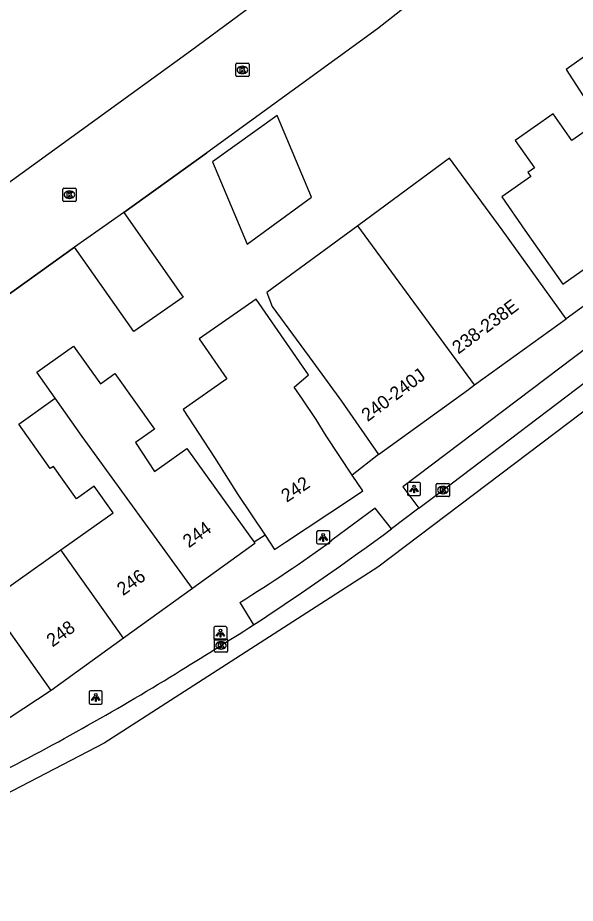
# Model space of a CAD drawing. Extents: x 159265 to 160143, y 383413 to 384319.
# Drawn here: x 159435.2 to 159477.4, y 383435.6 to 383502.5 of the extents above; entities that cross this region are included whole.
import ezdxf

# ---------------------------------------------------------------- set-up
doc = ezdxf.new("R2010")
doc.units = 0
for name, color, linetype in [('IMGEO_Kolk', 7, 'Continuous'), ('IMGEO_Lichtpunt', 7, 'Continuous'), ('IMGEO_Muur', 7, 'Continuous'), ('IMGEO_Pand', 7, 'Continuous'), ('IMGEO_Pand_nummerreeks', 7, 'Continuous'), ('IMGEO_Rijbaan_lokaal_gesloten', 7, 'Continuous'), ('IMGEO_Rijbaan_lokaal_open', 7, 'Continuous'), ('IMGEO_Rijbaan_regionaal_open', 7, 'Continuous'), ('IMGEO_Voetpad_open', 7, 'Continuous')]:
    doc.layers.add(name, color=color, linetype=linetype)

msp = doc.modelspace()

# ---------------------------------------------------------------- linework, layer by layer
at = {"layer": 'IMGEO_Kolk'}
for p, q in [((159451.715, 383498.137), (159451.715, 383498.989)), ((159451.79, 383499.063), (159452.642, 383499.063)), ((159452.716, 383498.989), (159452.716, 383498.137)), ((159452.226, 383498.283), (159452.201, 383498.283)), ((159452.203, 383498.843), (159452.228, 383498.843)), ((159452.642, 383498.063), (159451.79, 383498.063)), ((159438.627, 383488.701), (159438.627, 383489.553)), ((159438.702, 383489.627), (159439.554, 383489.627)), ((159439.628, 383489.553), (159439.628, 383488.701)), ((159439.138, 383488.847), (159439.113, 383488.847)), ((159439.115, 383489.407), (159439.14, 383489.407)), ((159439.554, 383488.627), (159438.702, 383488.627)), ((159466.884, 383466.372), (159466.884, 383467.224)), ((159466.959, 383467.298), (159467.811, 383467.298)), ((159467.372, 383467.078), (159467.397, 383467.078)), ((159467.885, 383467.224), (159467.885, 383466.372)), ((159467.811, 383466.298), (159466.959, 383466.298)), ((159467.395, 383466.518), (159467.37, 383466.518)), ((159450.097, 383454.623), (159450.097, 383455.475)), ((159450.172, 383455.549), (159451.024, 383455.549)), ((159451.098, 383455.475), (159451.098, 383454.623)), ((159450.608, 383454.769), (159450.583, 383454.769)), ((159450.585, 383455.329), (159450.61, 383455.329)), ((159451.024, 383454.549), (159450.172, 383454.549))]:
    msp.add_line(p, q, dxfattribs=at)
for points in [[(159451.715, 383498.137), (159451.715, 383498.989)], [(159451.79, 383499.063), (159452.642, 383499.063)], [(159452.716, 383498.989), (159452.716, 383498.137)], [(159452.036, 383498.763), (159452.159, 383498.763), (159452.159, 383498.612), (159452.289, 383498.763), (159452.453, 383498.763), (159452.307, 383498.612), (159452.46, 383498.363), (159452.308, 383498.363), (159452.223, 383498.527), (159452.159, 383498.46), (159452.159, 383498.363), (159452.036, 383498.363), (159452.036, 383498.763)], [(159452.642, 383498.063), (159451.79, 383498.063)], [(159438.627, 383488.701), (159438.627, 383489.553)], [(159438.702, 383489.627), (159439.554, 383489.627)], [(159439.628, 383489.553), (159439.628, 383488.701)], [(159438.948, 383489.327), (159439.071, 383489.327), (159439.071, 383489.176), (159439.201, 383489.327), (159439.365, 383489.327), (159439.219, 383489.176), (159439.372, 383488.927), (159439.22, 383488.927), (159439.135, 383489.091), (159439.071, 383489.024), (159439.071, 383488.927), (159438.948, 383488.927), (159438.948, 383489.327)], [(159439.554, 383488.627), (159438.702, 383488.627)], [(159466.884, 383466.372), (159466.884, 383467.224)], [(159466.959, 383467.298), (159467.811, 383467.298)], [(159467.205, 383466.998), (159467.328, 383466.998), (159467.328, 383466.847), (159467.458, 383466.998), (159467.622, 383466.998), (159467.476, 383466.847), (159467.629, 383466.598), (159467.477, 383466.598), (159467.392, 383466.762), (159467.328, 383466.695), (159467.328, 383466.598), (159467.205, 383466.598), (159467.205, 383466.998)], [(159467.885, 383467.224), (159467.885, 383466.372)], [(159467.811, 383466.298), (159466.959, 383466.298)], [(159450.097, 383454.623), (159450.097, 383455.475)], [(159450.172, 383455.549), (159451.024, 383455.549)], [(159451.098, 383455.475), (159451.098, 383454.623)], [(159450.418, 383455.249), (159450.541, 383455.249), (159450.541, 383455.098), (159450.671, 383455.249), (159450.835, 383455.249), (159450.689, 383455.098), (159450.842, 383454.849), (159450.69, 383454.849), (159450.605, 383455.013), (159450.541, 383454.946), (159450.541, 383454.849), (159450.418, 383454.849), (159450.418, 383455.249)], [(159451.024, 383454.549), (159450.172, 383454.549)]]:
    msp.add_lwpolyline(points, dxfattribs=at)
for centre, start, end in [((159451.792, 383498.987), 91.55205, 178.44795), ((159451.792, 383498.987), 91.55205, 178.44795), ((159452.64, 383498.987), 1.55205, 88.44795), ((159452.64, 383498.987), 1.55205, 88.44795), ((159451.792, 383498.139), 181.55205, 268.44795), ((159451.792, 383498.139), 181.55205, 268.44795), ((159452.64, 383498.139), 271.55205, 358.44795), ((159452.64, 383498.139), 271.55205, 358.44795), ((159438.704, 383489.551), 91.55205, 178.44795), ((159438.704, 383489.551), 91.55205, 178.44795), ((159439.552, 383489.551), 1.55205, 88.44795), ((159439.552, 383489.551), 1.55205, 88.44795), ((159438.704, 383488.703), 181.55205, 268.44795), ((159438.704, 383488.703), 181.55205, 268.44795), ((159439.552, 383488.703), 271.55205, 358.44795), ((159439.552, 383488.703), 271.55205, 358.44795), ((159466.961, 383467.222), 91.55205, 178.44795), ((159466.961, 383467.222), 91.55205, 178.44795), ((159467.809, 383467.222), 1.55205, 88.44795), ((159467.809, 383467.222), 1.55205, 88.44795), ((159466.961, 383466.374), 181.55205, 268.44795), ((159466.961, 383466.374), 181.55205, 268.44795), ((159467.809, 383466.374), 271.55205, 358.44795), ((159467.809, 383466.374), 271.55205, 358.44795), ((159450.174, 383455.473), 91.55205, 178.44795), ((159450.174, 383455.473), 91.55205, 178.44795), ((159451.022, 383455.473), 1.55205, 88.44795), ((159451.022, 383455.473), 1.55205, 88.44795), ((159450.174, 383454.625), 181.55205, 268.44795), ((159450.174, 383454.625), 181.55205, 268.44795), ((159451.022, 383454.625), 271.55205, 358.44795), ((159451.022, 383454.625), 271.55205, 358.44795)]:
    msp.add_arc(centre, 0.0765, start, end, dxfattribs=at)
for centre, major_axis, ratio, start_param, end_param in [((159452.202, 383498.563), (-0.387, 0.002), 0.722429, 4.712389, 7.853982), ((159452.227, 383498.563), (-0.39, 0.002), 0.717154, 1.570796, 4.712389), ((159439.114, 383489.127), (-0.387, 0.002), 0.722429, 4.712389, 7.853982), ((159439.139, 383489.127), (-0.39, 0.002), 0.717154, 1.570796, 4.712389), ((159467.371, 383466.798), (-0.387, 0.002), 0.722429, 4.712389, 7.853982), ((159467.396, 383466.798), (-0.39, 0.002), 0.717154, 1.570796, 4.712389), ((159450.584, 383455.049), (-0.387, 0.002), 0.722429, 4.712389, 7.853982), ((159450.609, 383455.049), (-0.39, 0.002), 0.717154, 1.570796, 4.712389)]:
    msp.add_ellipse(centre, major_axis=major_axis, ratio=ratio, start_param=start_param, end_param=end_param, dxfattribs=at)
at = {"layer": 'IMGEO_Lichtpunt'}
for p, q in [((159464.701, 383467.281), (159464.701, 383466.474)), ((159464.701, 383467.281), (159464.701, 383466.474)), ((159465.603, 383467.376), (159464.795, 383467.376)), ((159465.603, 383467.376), (159464.795, 383467.376)), ((159465.697, 383466.474), (159465.697, 383467.281)), ((159465.697, 383466.474), (159465.697, 383467.281)), ((159464.795, 383466.38), (159465.603, 383466.38)), ((159464.795, 383466.38), (159465.603, 383466.38)), ((159457.833, 383463.62), (159457.833, 383462.813)), ((159457.833, 383463.62), (159457.833, 383462.813)), ((159458.735, 383463.715), (159457.927, 383463.715)), ((159458.735, 383463.715), (159457.927, 383463.715)), ((159458.829, 383462.813), (159458.829, 383463.62)), ((159458.829, 383462.813), (159458.829, 383463.62)), ((159457.927, 383462.719), (159458.735, 383462.719)), ((159457.927, 383462.719), (159458.735, 383462.719)), ((159450.054, 383456.373), (159450.054, 383455.566)), ((159450.054, 383456.373), (159450.054, 383455.566)), ((159450.956, 383456.468), (159450.148, 383456.468)), ((159450.956, 383456.468), (159450.148, 383456.468)), ((159451.05, 383455.566), (159451.05, 383456.373)), ((159451.05, 383455.566), (159451.05, 383456.373)), ((159450.148, 383455.472), (159450.956, 383455.472)), ((159450.148, 383455.472), (159450.956, 383455.472)), ((159440.618, 383451.514), (159440.618, 383450.707)), ((159440.618, 383451.514), (159440.618, 383450.707)), ((159441.52, 383451.609), (159440.712, 383451.609)), ((159441.52, 383451.609), (159440.712, 383451.609)), ((159441.614, 383450.707), (159441.614, 383451.514)), ((159441.614, 383450.707), (159441.614, 383451.514)), ((159440.712, 383450.613), (159441.52, 383450.613)), ((159440.712, 383450.613), (159441.52, 383450.613))]:
    msp.add_line(p, q, dxfattribs=at)
for points in [[(159465.075, 383466.945), (159465.114, 383466.917), (159464.926, 383466.655), (159464.888, 383466.682), (159465.075, 383466.945)], [(159465.177, 383466.897), (159465.224, 383466.897), (159465.224, 383466.575), (159465.177, 383466.575), (159465.177, 383466.897)], [(159465.287, 383466.917), (159465.325, 383466.944), (159465.512, 383466.682), (159465.473, 383466.654), (159465.287, 383466.917)], [(159458.207, 383463.284), (159458.246, 383463.256), (159458.058, 383462.994), (159458.02, 383463.021), (159458.207, 383463.284)], [(159458.309, 383463.236), (159458.356, 383463.236), (159458.356, 383462.914), (159458.309, 383462.914), (159458.309, 383463.236)], [(159458.419, 383463.256), (159458.457, 383463.283), (159458.644, 383463.021), (159458.605, 383462.993), (159458.419, 383463.256)], [(159450.428, 383456.037), (159450.467, 383456.009), (159450.279, 383455.747), (159450.241, 383455.774), (159450.428, 383456.037)], [(159450.64, 383456.009), (159450.678, 383456.036), (159450.865, 383455.774), (159450.826, 383455.746), (159450.64, 383456.009)], [(159450.53, 383455.989), (159450.577, 383455.989), (159450.577, 383455.667), (159450.53, 383455.667), (159450.53, 383455.989)], [(159440.992, 383451.178), (159441.031, 383451.15), (159440.843, 383450.888), (159440.805, 383450.915), (159440.992, 383451.178)], [(159441.094, 383451.13), (159441.141, 383451.13), (159441.141, 383450.808), (159441.094, 383450.808), (159441.094, 383451.13)], [(159441.204, 383451.15), (159441.242, 383451.177), (159441.429, 383450.915), (159441.39, 383450.887), (159441.204, 383451.15)]]:
    msp.add_lwpolyline(points, dxfattribs=at)
for centre in [(159465.2, 383467.079), (159458.332, 383463.418), (159450.553, 383456.171), (159441.117, 383451.312)]:
    msp.add_circle(centre, 0.0994, dxfattribs=at)
for centre, start, end in [((159464.795, 383467.281), 90, 180), ((159464.795, 383467.281), 90, 180), ((159465.603, 383467.281), 0, 90), ((159465.603, 383467.281), 0, 90), ((159464.795, 383466.474), 180, 270), ((159464.795, 383466.474), 180, 270), ((159465.603, 383466.474), 270, 0), ((159465.603, 383466.474), 270, 360), ((159457.927, 383463.62), 90, 180), ((159457.927, 383463.62), 90, 180), ((159458.735, 383463.62), 0, 90), ((159458.735, 383463.62), 0, 90), ((159457.927, 383462.813), 180, 270), ((159457.927, 383462.813), 180, 270), ((159458.735, 383462.813), 270, 0), ((159458.735, 383462.813), 270, 360), ((159450.148, 383456.373), 90, 180), ((159450.148, 383456.373), 90, 180), ((159450.956, 383456.373), 0, 90), ((159450.956, 383456.373), 0, 90), ((159450.148, 383455.566), 180, 270), ((159450.148, 383455.566), 180, 270), ((159450.956, 383455.566), 270, 0), ((159450.956, 383455.566), 270, 360), ((159440.712, 383451.514), 90, 180), ((159440.712, 383451.514), 90, 180), ((159441.52, 383451.514), 0, 90), ((159441.52, 383451.514), 0, 90), ((159440.712, 383450.707), 180, 270), ((159440.712, 383450.707), 180, 270), ((159441.52, 383450.707), 270, 0), ((159441.52, 383450.707), 270, 360)]:
    msp.add_arc(centre, 0.0946, start, end, dxfattribs=at)
at = {"layer": 'IMGEO_Muur'}
for points in [[(159443.239, 383487.773), (159449.528, 383492.287)], [(159433.127, 383480.612), (159439.516, 383485.157)]]:
    msp.add_lwpolyline(points, dxfattribs=at)
at = {"layer": 'IMGEO_Pand'}
for points in [[(159479.715, 383500.7), (159479.502, 383500.551), (159478.714, 383500), (159476.722, 383498.608), (159479.236, 383494.693), (159477.15, 383493.229), (159475.729, 383495.254), (159472.856, 383493.238), (159474.313, 383491.16), (159473.807, 383490.805), (159474.025, 383490.493), (159471.836, 383488.957), (159473.59, 383486.458), (159476.462, 383482.365), (159478.788, 383483.997), (159479.087, 383483.571), (159479.745, 383484.033), (159481.015, 383484.146), (159481.399, 383484.415), (159481.953, 383485.607), (159484.71, 383487.541), (159484.476, 383487.874), (159486.045, 383488.975)], [(159457.437, 383488.954), (159454.845, 383495.109), (159449.955, 383491.613), (159452.588, 383485.395), (159457.437, 383488.954)], [(159476.722, 383479.744), (159471.871, 383486.477), (159467.89, 383491.891), (159460.937, 383486.78)], [(159443.239, 383487.773), (159447.724, 383481.391), (159444.002, 383478.776), (159439.516, 383485.157)], [(159443.239, 383487.773), (159439.516, 383485.157)], [(159460.937, 383486.78), (159454.059, 383481.723), (159454.459, 383480.686), (159457.543, 383476.49), (159459.724, 383473.523), (159462.522, 383469.489)], [(159469.787, 383474.742), (159460.937, 383486.78)], [(159460.521, 383467.934), (159458.557, 383470.895), (159457.797, 383472.131), (159456.764, 383473.668), (159456.127, 383474.578), (159457.221, 383475.501), (159453.26, 383481.225), (159448.946, 383478.232), (159451.032, 383475.216), (159447.745, 383472.893), (159450.098, 383469.247), (159451.881, 383466.465), (159453.93, 383463.377)], [(159469.787, 383474.742), (159476.722, 383479.744)], [(159438.061, 383473.754), (159436.671, 383475.711), (159439.443, 383477.681), (159441.471, 383474.828), (159442.571, 383475.61), (159445.555, 383471.413), (159444.125, 383470.396), (159445.561, 383468.206), (159448.009, 383469.938), (159450.825, 383466.011), (159453.099, 383462.856)], [(159462.522, 383469.489), (159469.311, 383474.399), (159469.787, 383474.742)], [(159438.488, 383462.279), (159442.428, 383465.079), (159440.998, 383467.093), (159439.662, 383466.144), (159437.925, 383468.59), (159437.681, 383468.417), (159435.289, 383471.784), (159438.061, 383473.754)], [(159448.436, 383459.357), (159440.09, 383470.84), (159438.061, 383473.754)], [(159453.93, 383463.377), (159454.645, 383462.299), (159455.487, 383462.857), (159460.48, 383466.17), (159461.322, 383466.728), (159460.521, 383467.934)], [(159437.735, 383451.642), (159433.488, 383457.629), (159429.789, 383462.846), (159432.239, 383464.634), (159434.006, 383462.148), (159432.67, 383461.199), (159434.113, 383459.17), (159438.488, 383462.279)], [(159453.099, 383462.856), (159453.164, 383462.766), (159448.436, 383459.357)], [(159443.209, 383455.589), (159438.488, 383462.279)], [(159448.436, 383459.357), (159443.209, 383455.589)], [(159443.209, 383455.589), (159437.735, 383451.642)]]:
    msp.add_lwpolyline(points, dxfattribs=at)
at = {"layer": 'IMGEO_Rijbaan_lokaal_gesloten'}
for points in [[(159465.574, 383465.42), (159467.385, 383466.798), (159479.598, 383476.059)], [(159465.574, 383465.42), (159463.506, 383463.865)]]:
    msp.add_lwpolyline(points, dxfattribs=at)
for centre, radius, start, end in [((159323.183, 383654.441), 236.664, 303.28379, 306.36455), ((159107.292, 384003.305), 646.872, 301.695618, 302.311656), ((159340.979, 383625.792), 202.885, 296.92369, 301.55861)]:
    msp.add_arc(centre, radius, start, end, dxfattribs=at)
at = {"layer": 'IMGEO_Rijbaan_lokaal_open'}
for points in [[(159473.83, 383510.649), (159462.427, 383501.672), (159449.528, 383492.287), (159443.239, 383487.773)], [(159439.516, 383485.157), (159433.127, 383480.612), (159429.309, 383486.278), (159448.278, 383500), (159458.947, 383507.895)]]:
    msp.add_lwpolyline(points, dxfattribs=at)
at = {"layer": 'IMGEO_Rijbaan_regionaal_open'}
msp.add_lwpolyline([(159490.279, 383481.992), (159462.471, 383460.966), (159441.755, 383447.67), (159418.461, 383435.551)], dxfattribs=at)
at = {"layer": 'IMGEO_Voetpad_open'}
for points in [[(159496.814, 383494.302), (159476.722, 383479.744)], [(159479.598, 383476.059), (159478.388, 383477.639), (159464.344, 383467.051), (159465.574, 383465.42)], [(159462.522, 383469.489), (159460.521, 383467.934)], [(159463.506, 383463.865), (159462.249, 383465.435), (159458.992, 383462.996)], [(159453.93, 383463.377), (159453.099, 383462.856)], [(159452.026, 383458.306), (159453.061, 383456.599)], [(159437.735, 383451.642), (159432.558, 383448.247)]]:
    msp.add_lwpolyline(points, dxfattribs=at)
msp.add_arc((159396.445, 383548.378), 105.841, 301.67761, 306.2248, dxfattribs=at)

# ---------------------------------------------------------------- texts
at = {"layer": 'IMGEO_Pand_nummerreeks'}
for s, rotation, p in [('238-238E', 36.75524, (159468.553, 383477.035)), ('240-240J', 36.71514, (159461.689, 383471.93)), ('242', 33.90191, (159455.572, 383465.828)), ('244', 35.99894, (159448.163, 383462.382)), ('246', 36.0104, (159443.182, 383458.762)), ('248', 36.00467, (159437.85, 383454.887))]:
    msp.add_text(s, height=1, rotation=rotation, dxfattribs=at).set_placement(p)

doc.saveas('drawing.dxf')
